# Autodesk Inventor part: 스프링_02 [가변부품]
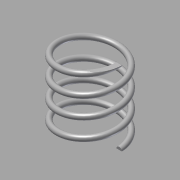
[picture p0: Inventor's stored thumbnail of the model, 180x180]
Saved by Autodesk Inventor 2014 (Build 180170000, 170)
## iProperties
Created: 2015-07
Part Number: 스프링_02 [가변부품]
Material: 강철, 연강
Document SubType Name: Modeling
Designer: Administrator
Mass: 2.75026 g
Surface Area: 9.46921 cm^2
Volume: 0.349906 cm^3
Density: 7.86 g/cm^3
Appearance: 강철
Author: Administrator
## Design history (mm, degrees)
sketch "스케치1"
  geometry: L1 (0, 0)-(-8, 0); L2 (-8, 0)-(-8, 20.5); L3 (-8, 20.5)-(0, 20.5); L4 (0, 20.5)-(0, 0); C1 r 0.75 at (-8, 0)
  constraints: 8 end point, 2 parallel, 1 centre point, 1 coincident, 1 horizontal, 1 perpendicular
  dimensions: "d0" = 16 diameter of L2 L4; "d1" = 20.5 distance of L1.end L2.end (derived); "d2" = 1.5 diameter of C1
feature "코일1" sketch "스케치1" pitch "d3" = 10; turns "d5" = 4; dims "d4" = 20.5 (= d1), "d6" = 0, angle "d7" = 90 deg, angle "d8" = 90 deg, "d9" = 0, "d10" = 0
node "작업 평면1"
sketch "스케치2"
  geometry: L1 (-0.75, 0)-(0.75, 0) reference; 1 further point
  constraints: 1 horizontal alignment
extrude "돌출1" cut sketch "스케치2" distance "d11" = 10; taper "d12" = 0 deg
node "작업 평면2"
sketch "스케치3"
  geometry: L1 (0.75, 0)-(-0.75, 0) reference; 1 further point
  constraints: 1 horizontal alignment
extrude "돌출2" cut sketch "스케치3" distance "d13" = 10; taper "d14" = 0 deg
node "솔리드1"
node "절단 모서리 투영1"
node "절단 모서리 투영2"
